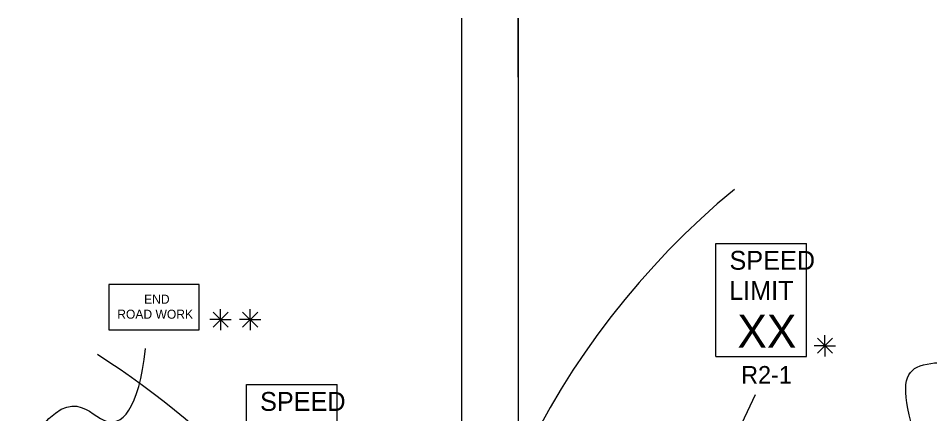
# Model space of a CAD drawing. Extents: x 16728 to 19508, y 5553 to 7079.
# Drawn here: x 16792.7 to 17179.3, y 6806.3 to 6974.1 of the extents above; entities that cross this region are included whole.
import ezdxf

# ---------------------------------------------------------------- set-up
doc = ezdxf.new("R2010")
doc.units = 0
for name, color, linetype in [('ALI_LEGAL_EX', 7, 'Continuous'), ('TRAFFIC_SIGNS_PR', 7, 'Continuous'), ('TYPICAL_TEXT_DIMEN_PR', 7, 'Continuous')]:
    doc.layers.add(name, color=color, linetype=linetype)

msp = doc.modelspace()

# ---------------------------------------------------------------- linework, layer by layer
at = {"layer": 'ALI_LEGAL_EX'}
for p, q in [((16980.68, 6974.12), (16980.68, 6155.98)), ((17004.68, 6974.12), (17004.68, 6155.98)), ((16980.68, 6877.04), (16980.68, 6013.12)), ((17004.68, 6877.04), (17004.68, 6013.12))]:
    msp.add_line(p, q, dxfattribs=at)
msp.add_lwpolyline([(17004.68, 6949.12), (17004.68, 6974.12)], dxfattribs=at)
for centre, radius, start, end in [((17313.01, 6639.38), 340, 129.5666, 180), ((16629.65, 6525.15), 364, 0, 57.2958)]:
    msp.add_arc(centre, radius, start, end, dxfattribs=at)
at = {"layer": 'TRAFFIC_SIGNS_PR'}
for p, q in [((17088.62, 6878.56), (17127.01, 6878.56)), ((17088.62, 6830.56), (17088.62, 6878.56)), ((17127.01, 6830.56), (17127.01, 6878.56)), ((17088.62, 6830.56), (17127.01, 6830.56)), ((16889.53, 6818.69), (16927.92, 6818.69)), ((16889.53, 6770.69), (16889.53, 6818.69)), ((16927.92, 6770.69), (16927.92, 6818.69))]:
    msp.add_line(p, q, dxfattribs=at)
msp.add_lwpolyline([(16831.1, 6841.89), (16869.5, 6841.89), (16869.5, 6861.09), (16831.1, 6861.09)], close=True, dxfattribs=at)
at = {"layer": 'TYPICAL_TEXT_DIMEN_PR'}
for p, q in [((16878.52, 6846.27), (16878.52, 6850.73)), ((16891.08, 6846.27), (16891.08, 6850.73)), ((16881.71, 6849.46), (16875.33, 6843.08)), ((16875.34, 6849.46), (16881.71, 6843.08)), ((16887.89, 6849.46), (16894.27, 6843.08)), ((16894.27, 6849.46), (16887.89, 6843.08)), ((16878.52, 6846.27), (16873.99, 6846.27)), ((16878.52, 6846.27), (16881.71, 6846.27)), ((16878.52, 6846.27), (16883, 6846.27)), ((16878.52, 6846.27), (16878.52, 6841.77)), ((16891.08, 6846.27), (16886.55, 6846.27)), ((16891.08, 6846.27), (16894.27, 6846.27)), ((16891.08, 6846.27), (16895.56, 6846.27)), ((16891.08, 6846.27), (16891.08, 6841.77)), ((17134.82, 6835.17), (17134.82, 6839.63)), ((17131.64, 6838.36), (17138.01, 6831.99)), ((17138.01, 6838.36), (17131.64, 6831.99)), ((17134.82, 6835.17), (17130.29, 6835.17)), ((17134.82, 6835.17), (17138.01, 6835.17)), ((17134.82, 6835.17), (17139.3, 6835.17)), ((17134.82, 6835.17), (17134.82, 6830.67)), ((17077.28, 6754.99), (17105.34, 6814.46))]:
    msp.add_line(p, q, dxfattribs=at)
for points in [[(16792.71, 6785.53), (16812.75, 6822.09), (16829.8, 6792), (16843.76, 6808.28), (16846.76, 6833.99)], [(17174.09, 6792.93), (17168.08, 6812.93), (17166.46, 6830.47), (17190.65, 6827.96), (17196.93, 6827.39)]]:
    msp.add_open_spline(points, degree=3, dxfattribs=at)

# ---------------------------------------------------------------- texts
at = {"layer": 'TRAFFIC_SIGNS_PR'}
for s, height, p in [('SPEED', 8, (17094.38, 6867.42)), ('LIMIT', 8, (17094.22, 6854.62)), ('END', 3.831, (16846.1, 6853.02)), ('ROAD WORK', 3.831, (16834.7, 6846.64)), ('XX', 14.031, (17097.73, 6834.32)), ('R2-1', 7.44, (17099.29, 6819.12)), ('SPEED', 8, (16895.29, 6807.55))]:
    msp.add_text(s, height=height, dxfattribs=at).set_placement(p)

doc.saveas('drawing.dxf')
